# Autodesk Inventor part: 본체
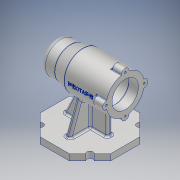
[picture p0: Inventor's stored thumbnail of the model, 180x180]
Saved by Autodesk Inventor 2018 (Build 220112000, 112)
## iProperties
Created: 2019-12
Part Number: 본체
Material: 알루미늄 6061
Document SubType Name: Modeling
Designer: USER
Density: 2.7 g/cm^3
Appearance: 알루미늄 - 평지
Mass: 743.465 g
Surface Area: 717.835 cm^2
Volume: 275.358 cm^3
Author: USER
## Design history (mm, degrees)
sketch "스케치1"
  geometry: L1 (0, 0)-(132.064, 0); L2 (0, 0)-(0, 25); L3 (0, 25)-(25, 25); L4 (25, 25)-(45, 30); L5 (45, 30)-(112, 30); L6 (112, 30)-(112, 21); L7 (97, 21)-(97, 21); L8 (94, 24)-(46, 24); L9 (43, 21)-(43, 21); L10 (43, 21)-(31, 21); L11 (31, 21)-(31, 17.5); L12 (31, 17.5)-(13, 17.5); L13 (13, 17.5)-(13, 16); L14 (13, 16)-(9, 16); L15 (9, 16)-(9, 10.5); L16 (9, 10.5)-(9, 10.5); L17 (6, 7.5)-(6, 0); L18 (97, 21)-(112, 21); L19 (0, 0)-(6, 0); A1 r 3 centre (9, 7.5) between (9, 10.5) and (6, 7.5); A2 r 3 centre (46, 21) between (46, 24) and (43, 21); A3 r 3 centre (94, 21) between (97, 21) and (94, 24)
  constraints: 38 end point, 12 perpendicular, 6 point on circle, 6 tangent, 3 centre point, 2 equal radius, 2 horizontal, 2 vertical, 1 collinear, 1 parallel
  dimensions: "d0" = 25 distance of L1.start L2.end; "d1" = 25 distance of L2.end L3.end; "d4" = 112 distance between parallel lines of L2 L6; "d5" = 30 distance between parallel lines of L1 L5; "d7" = 15 distance of L6.end L7.start; "d8" = 21 distance between parallel lines of L1 L18; "d9" = 24 distance between parallel lines of L1 L8; "d15" = 16 distance between parallel lines of L1 L14; "d20" = 17.5 distance between parallel lines of L1 L12; "d21" = 21 distance between parallel lines of L1 L10; "d97" = 54 distance of L7.start L9.end; "d98" = 45 distance from line of L2 L4.end; "d101" = 12 distance from line of L9.start L11; "d102" = 18 distance from line of L11.end L13; "d103" = 4 distance from line of L13.end L15; "d104" = 6 distance between parallel lines of L2 L17; "d106" = 9 distance from line of L2 A1.centre (derived); "d107" = 3 radius of A2; "d108" = 10.5 distance from line of L1 L15.end
revolve "회전2" sketch "스케치1" stored, may be unused: angle "d22" = 90 deg
sketch "스케치3"
  geometry: L1 (0, 0)-(0, 57.725); L2 (0, 0)-(-52.854, 0); C1 r 30 at (0, 0); C2 r 6 at (-30, 0); 2 further points
  constraints: 4 end point, 2 centre point, 1 coincident, 1 horizontal, 1 horizontal alignment, 1 point on line, 1 vertical, 1 other
  dimensions: "d23" = 60 diameter of C1; "d24" = 12 diameter of C2
extrude "돌출1" join sketch "스케치3" distance "d25" = 16; taper "d26" = 0 deg
sketch "스케치4"
  geometry: A1 r 6 centre (0, 0) between (0.6, 5.97) and (0.6, -5.97) reference; 2 further points
  constraints: 1 coincident
hole "구멍1" sketch "스케치4" at (0, 0) diameter "d27" = 3.242; stored, may be unused: countersink angle "d31" = 90 deg, drill point angle "d33" = 118 deg; dims "d28" = 8, "d29" = 4, "d30" = 2, "d32" = 11
node "작업 평면1"
sketch "스케치5"
  geometry: L1 (0, 0)-(112, 0); L2 (0, 0)-(0, 112); L3 (56, 64.671)-(56, 0); L4 (0, 23.196)-(32.804, 56); L5 (32.804, 56)-(79.196, 56); L6 (79.196, 56)-(112, 23.196); L7 (112, 23.196)-(112, -23.196); L8 (112, -23.196)-(79.196, -56); L9 (79.196, -56)-(32.804, -56); L10 (32.804, -56)-(0, -23.196); L11 (0, -23.196)-(0, 23.196); 1 further point
  constraints: 22 end point, 1 coincident, 1 horizontal, 1 point on line, 1 vertical, 17 other
  dimensions: "d38" = 112 distance of L1.start L1.end; "d39" = 112 distance of L1.start L2.end; "d40" = 56 distance between parallel lines of L2 L3; "d41" = 180 deg angle of L2 L11; "d42" = 0 distance from line of L1 L3.end
extrude "돌출2" join sketch "스케치5" distance "d43" = 10; taper "d44" = 0 deg
sketch "스케치6"
  geometry: L1 (0, 0)-(56, 0); L2 (56, 0)-(95.598, 39.598); L3 (79.196, 56)-(112, 23.196) reference; L4 (56, 0)-(112, 0); C1 r 56 at (56, 0); C2 r 5 at (95.598, 39.598); C3 r 5 at (16.402, 39.598); C4 r 5 at (16.402, -39.598); C5 r 5 at (95.598, -39.598)
  constraints: 6 end point, 5 centre point, 2 coincident, 2 horizontal, 1 equal length, 1 midpoint, 9 other
  dimensions: "d45" = 56 distance of L1.start L1.end; "d46" = 112 diameter of C1; "d47" = 45 deg angle of L4 L2 (derived); "d48" = 10 diameter of C2; "d53" = 360 deg dimension on L2.start C2.centre (derived)
extrude "돌출4" cut sketch "스케치6" distance "d55" = 10; taper "d56" = 0 deg
fillet "모깎기1" dims "d57" = 0.3
sketch "스케치7"
  geometry: L1 (0, 0)-(150.369, 0); L2 (0, 0)-(0, 79.943); L3 (56, 76.136)-(56, -74.333); L4 (18, -3.594)-(87, -3.594); L5 (87, -3.594)-(87, 4.406); L6 (87, 4.406)-(18, 4.406); L7 (18, 4.406)-(18, -3.594); L8 (87, -3.594)-(18, 4.406); L9 (112, 23.196)-(112, -23.196) reference; L10 (32.804, 56)-(79.196, 56) reference; 2 further points
  constraints: 16 end point, 3 point on line, 2 horizontal, 2 parallel, 2 vertical, 1 midpoint, 1 perpendicular
  dimensions: "d58" = 56 distance between parallel lines of L2 L3; "d59" = 8 distance of L5.end L4.end; "d61" = 18 distance between parallel lines of L2 L7; "d62" = 25 distance between parallel lines of L9 L5
extrude "돌출6" join sketch "스케치7" distance "d68" = 45; taper "d69" = 0 deg
feature "면 기울기1" dims angle "d70" = 25 deg
sketch "스케치8"
  geometry: L1 (0, 0)-(56, 0); L2 (60, 36)-(52, 36); L3 (52, 36)-(52, -36); L4 (52, -36)-(60, -36); L5 (60, -36)-(60, 36); L6 (60, 36)-(52, -36); L7 (52, 36)-(60, -36)
  constraints: 14 end point, 2 horizontal, 2 midpoint, 2 parallel, 1 perpendicular
  dimensions: "d71" = 56 distance of L1.start L1.end; "d72" = 8 distance of L4.end L3.end; "d73" = 72 distance of L3.end L2.end
extrude "돌출7" join sketch "스케치8" distance "d74" = 50; taper "d75" = 0 deg
feature "면 기울기2" dims angle "d76" = 20 deg
feature "면 기울기3" dims angle "d77" = 20 deg
sketch "스케치9"
  geometry: C1 r 24 at (0, 0) reference; C2 r 24 at (0, 0); 1 further point
  constraints: 1 centre point, 1 coincident
  dimensions: "d78" = 48 diameter of C2
extrude "돌출8" cut sketch "스케치9" distance "d79" = 10; taper "d80" = 0 deg
fillet "모깎기2" dims "d81" = 1
fillet "모깎기4" dims "d83" = 3
fillet "모깎기5" dims "d84" = 3
fillet "모깎기6" dims "d85" = 2
node "작업 평면3"
sketch "스케치11"
  geometry: L1 (0, 0)-(-136.481, 0); L2 (0, 22)-(0, -22) reference; 1 further point
  constraints: 2 end point, 1 horizontal, 1 other
  dimensions: "d88" = 0 distance from line of L1 point (-71, 0); "d92" = 71 distance from line of L2 point (-71, 0)
feature "엠보싱1" sketch "스케치11" dims "d0" = 25, "d1" = 25, "d4" = 112, "d5" = 30, "d7" = 15, "d8" = 21, "d9" = 24, "d15" = 16, "d20" = 17.5, "d21" = 21, "d90" = 0.5, "d91" = 0, "d97" = 54, "d98" = 45, "d101" = 12, "d102" = 18, "d103" = 4, "d104" = 6, "d106" = 9 (derived), "d107" = 3, "d108" = 10.5
fillet "모깎기7" dims "d93" = 10
fillet "모깎기8" dims "d94" = 3
node "솔리드2"
pattern_circular "원형 패턴1" dims angle "d35" = 360 deg
